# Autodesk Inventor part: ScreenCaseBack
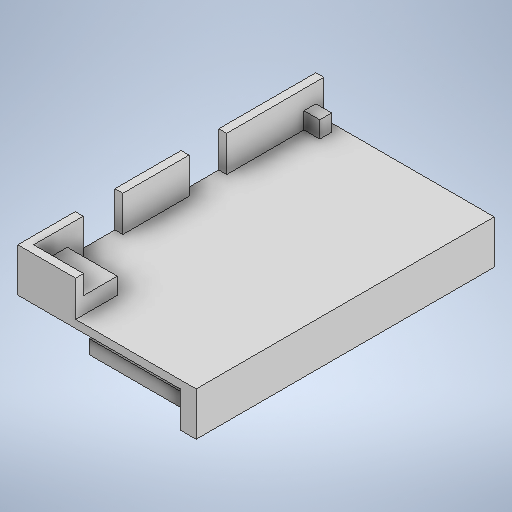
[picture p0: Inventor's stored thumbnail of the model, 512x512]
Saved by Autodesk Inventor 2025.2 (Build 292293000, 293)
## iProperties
Created: 2025-12
Part Number: ScreenCaseBack
Material: Generic
Document SubType Name: Modeling
Designer: tyler
Density: 1 g/cm^3
Appearance: Default
Author: tyler
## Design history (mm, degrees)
sketch "Sketch1"
  geometry: L1 (-26.035, 45.212)-(26.035, 45.212); L2 (26.035, 45.212)-(26.035, -45.212); L3 (26.035, -45.212)-(-26.035, -45.212); L4 (-26.035, -45.212)-(-26.035, 45.212); L5 (-26.035, 45.212)-(26.035, -45.212); L6 (26.035, 45.212)-(-26.035, -45.212); L7 (-28.575, 47.752)-(28.575, 47.752); L8 (28.575, 47.752)-(28.575, -47.752); L9 (28.575, -47.752)-(-28.575, -47.752); L10 (-28.575, -47.752)-(-28.575, 47.752); L11 (-28.575, 47.752)-(28.575, -47.752); L12 (28.575, 47.752)-(-28.575, -47.752); 1 further point
  constraints: 24 end point, 4 midpoint, 4 parallel, 2 horizontal, 2 perpendicular
  dimensions: "d0" = 52.07 distance of L2.end L3.end; "d1" = 90.424 distance of L1.end L2.end; "d2" = 57.15 distance of L8.end L9.end; "d3" = 95.504 distance of L7.end L8.end
extrude "Extrusion1" new body sketch "Sketch1" distance "d4" = 2.54; taper "d5" = 0 deg
sketch "Sketch2"
  geometry: L1 (-26.035, -45.212)-(26.035, -45.212); L2 (26.035, -45.212)-(26.035, 45.212); L3 (26.035, 45.212)-(-26.035, 45.212); L4 (-26.035, 45.212)-(-26.035, -45.212); L5 (-26.035, -45.212)-(26.035, 45.212); L6 (26.035, -45.212)-(-26.035, 45.212); L7 (-26.035, -45.212)-(-10.033, -45.212); L8 (-10.033, -45.212)-(-10.033, -47.752); L9 (-28.575, -47.752)-(28.575, -47.752) reference; L10 (-26.035, -45.212)-(-26.035, -29.337); L11 (-26.035, -29.337)-(-28.575, -29.337); L12 (-26.035, -45.212)-(-26.035, -16.637); L13 (-26.035, -16.637)-(-28.575, -16.637); L14 (-26.035, 45.212)-(-26.035, 16.637); L15 (-26.035, 16.637)-(-28.575, 16.637); L16 (-26.035, 45.212)-(-26.035, 4.572); L17 (-26.035, 4.572)-(-28.575, 4.572); L18 (-26.035, 45.212)-(-26.035, 47.752); L19 (28.575, 47.752)-(-28.575, 47.752) reference; L20 (28.575, 47.752)-(-28.575, 47.752); L21 (-28.575, 47.752)-(-28.575, -47.752); L22 (-28.575, -47.752)-(28.575, -47.752); L23 (28.575, -47.752)-(28.575, 47.752); L24 (28.575, 47.752)-(-28.575, -47.752); L25 (-28.575, 47.752)-(28.575, -47.752); 6 further points
  constraints: 46 end point, 7 perpendicular, 7 point on line, 4 midpoint, 4 parallel, 2 horizontal, 1 vertical
  dimensions: "d6" = 52.07 distance of L3.end L2.end; "d7" = 90.424 distance of L2.end L1.end; "d8" = 16.002 distance of L1.start L7.end; "d9" = 15.875 distance of L1.start L10.end; "d10" = 28.575 distance of L1.start L12.end; "d11" = 28.575 distance of L3.end L14.end; "d12" = 40.64 distance of L3.end L16.end
extrude "Extrusion2" join sketch "Sketch2" distance "d13" = 11.43; taper "d14" = 0 deg
sketch "Sketch3"
  geometry: L1 (0, 0)-(0, 11.43) reference; L2 (0, 0)-(0, 5.334); L3 (0, 5.334)-(16.219, 5.334); L4 (16.219, 5.334)-(16.219, 0); L5 (16.219, 0)-(0, 0); 1 further point
  constraints: 8 end point, 3 perpendicular, 1 point on line
  dimensions: "d15" = 5.334 distance of L1.start L2.end
extrude "Extrusion3" join sketch "Sketch3" distance "d19" = 10.795; taper "d20" = 0 deg
sketch "Sketch4"
  geometry: L1 (-64.389, 0)-(31.115, 0) reference; L2 (31.115, 0)-(31.115, 5.334); L3 (31.115, -2.54)-(31.115, 11.43) reference; L4 (31.115, 5.334)-(24.765, 5.334); L5 (24.765, 5.334)-(24.765, 0); L6 (24.765, 0)-(31.115, 0); L7 (31.115, 5.334)-(28.575, 5.334); L8 (28.575, 5.334)-(28.575, 0); 3 further points
  constraints: 12 end point, 4 perpendicular, 3 point on line
  dimensions: "d21" = 5.334 distance of L1.end L2.end; "d22" = 6.35 distance of L2.end L4.end; "d56" = 2.54 distance of L2.end L7.end
extrude "Extrusion4" join sketch "Sketch4" distance "d23" = 5.08; taper "d24" = 0 deg
sketch "Sketch7"
  geometry: L1 (28.575, -47.752)-(-28.575, -47.752) reference; L2 (28.575, -47.752)-(23.495, -47.752); L3 (28.575, 47.752)-(28.575, -47.752) reference; L4 (28.575, -47.752)-(28.575, 47.752); L5 (28.575, 47.752)-(23.495, 47.752); L6 (23.495, 47.752)-(23.495, -47.752); 1 further point
  constraints: 8 end point, 2 perpendicular, 1 collinear, 1 point on line
  dimensions: "d34" = 5.08 distance of L1.start L2.end
extrude "Extrusion7" join sketch "Sketch7" distance "d35" = 11.43; taper "d36" = 0 deg
sketch "Sketch8"
  geometry: L1 (95.504, -11.43)-(0, -11.43) reference; L2 (0, -11.43)-(0, -6.35); L3 (0, 2.54)-(0, -11.43) reference; L4 (95.504, -11.43)-(95.504, -6.985); L5 (95.504, -11.43)-(95.504, 2.54) reference; L6 (0, -11.43)-(6.35, -11.43); L7 (6.35, -11.43)-(6.35, -6.985); L8 (6.35, -6.985)-(19.05, -6.985); L9 (19.05, -6.985)-(19.05, -11.43); L10 (95.504, -11.43)-(89.154, -11.43); L11 (89.154, -11.43)-(89.154, -6.985); L12 (89.154, -6.985)-(76.454, -6.985); L13 (76.454, -6.985)-(76.454, -11.43); L14 (47.752, -6.985)-(41.402, -6.985); L15 (41.402, -6.985)-(41.402, -11.43); L16 (47.752, -6.985)-(54.102, -6.985); L17 (54.102, -6.985)-(54.102, -11.43); 2 further points; 1 other entity
  constraints: 28 end point, 9 point on line, 4 perpendicular, 3 vertical, 10 other
  dimensions: "d37" = 5.08 distance of L1.end L2.end; "d38" = 4.445 distance of L1.start L4.end; "d39" = 6.35 distance of L1.end L6.end; "d40" = 12.7 distance of L7.end L8.end; "d41" = 6.35 distance of L1.start L10.end; "d42" = 12.7 distance of L11.end L12.end; "d43" = 6.35 distance of L14.start L14.end; "d44" = 6.35 distance of L14.start L16.end
extrude "Extrusion8" join sketch "Sketch8" distance "d45" = 35.56; taper "d46" = 0 deg
sketch "Sketch9"
  geometry: L1 (-12.065, -28.702)-(-12.065, -41.402) reference; L2 (-12.065, -35.052)-(28.575, -35.052); L3 (28.575, -47.752)-(28.575, 47.752) reference; L4 (-12.065, 6.35)-(-12.065, -6.35) reference; L5 (-12.065, 0)-(28.575, 0); L6 (-12.065, 28.702)-(-12.065, 41.402) reference; L7 (-12.065, 35.052)-(28.575, 35.052); L8 (-12.065, -35.052)-(-5.715, -35.052); C1 r 2.857 at (-5.715, -35.052); C2 r 2.857 at (-5.715, 0); C3 r 2.857 at (-5.715, 35.052); C4 r 2.857 at (12.797, -35.052); C5 r 2.857 at (12.797, 0); C6 r 2.857 at (12.797, 35.052); 1 further point
  constraints: 8 end point, 8 point on line, 6 centre point, 4 midpoint, 1 coincident, 1 horizontal, 1 parallel
  dimensions: "d47" = 6.35 distance of L2.start L8.end; "d48" = 5.715 diameter of C1; "d49" = 5.715 diameter of C2; "d50" = 5.715 diameter of C3; "d51" = 5.715 diameter of C4; "d52" = 5.715 diameter of C5; "d53" = 5.715 diameter of C6
extrude "Extrusion9" cut sketch "Sketch9" distance "d54" = 6.35; taper "d55" = 0 deg
body "Solid1"
